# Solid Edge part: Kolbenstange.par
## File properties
Username: bmolnar
Dokumentum tartalom típus: 0
Author: bmolnar
Last saved by: bmolnar
Revision: 88
Sűrűség: 0,000 kg/m^3
Pontosság: 0,990
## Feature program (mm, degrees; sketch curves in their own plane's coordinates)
base feature "unnamed BaseFeature 1"
sketch for "unnamed Protrusion 1" plane through (0, 0, -22.75) normal (0, 0, -1) x-axis (0, 1, 0)
  circle centre (0, 0) radius 31.5
extrude "unnamed Protrusion 1" add finite 10.75 along +normal
thread "unnamed Thread 1"
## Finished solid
Body 1: solid body, 17 faces, 23 edges, 8 vertices.
  Faces by surface: plane 8, cylinder 4, torus 3, cone 2
  Edges by curve: circle 13, line 6, ellipse 2, intersection 2
Bounding box of the edges (mm; curved faces can reach further): 63.000 x 63.000 x 134.500, from (-31.5, -31.5, -33.5) to (31.5, 31.5, 101).
Cylindrical faces by radius (mm): R5 x1, R6 x1, R8 x1, R31.5 x1
Conical faces (half-angle, radius in mm at the cone's reference point): 20 deg R5.5 x1, 60 deg R5.6 x1
Toroidal faces (ring radius, tube radius in mm): R5.4 r0.4 x2, R6.3 r1.7 x1
Planar faces by outward normal: +x 1, +z 3, -x 1, -z 1, oblique 2
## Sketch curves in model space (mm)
circle centre (0, 0, -22.75) radius 31.5
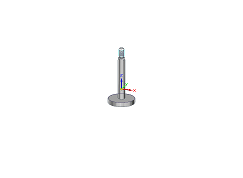
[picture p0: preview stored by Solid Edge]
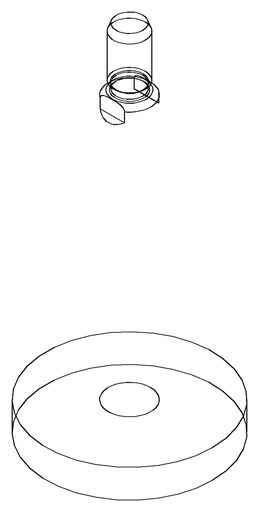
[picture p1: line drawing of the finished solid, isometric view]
